// Mitsubishi GX Works2 project: 步进电机画圆(王)   PLC: FX3U/FX3UC

PROGRAM MAIN
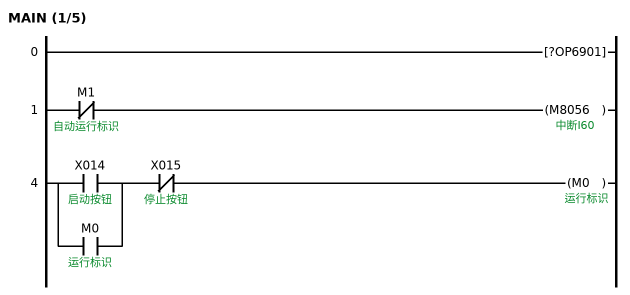
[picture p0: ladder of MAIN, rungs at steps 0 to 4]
0     ?OP6901
        [note] 允许中断(10ms中断一次)
1     LDI     M1  ; 自动运行标识
      OUT     M8056  ; 中断I60
4     LD      X014  ; 启动按钮
      OR      M0  ; 运行标识
      ANI     X015  ; 停止按钮
      OUT     M0  ; 运行标识
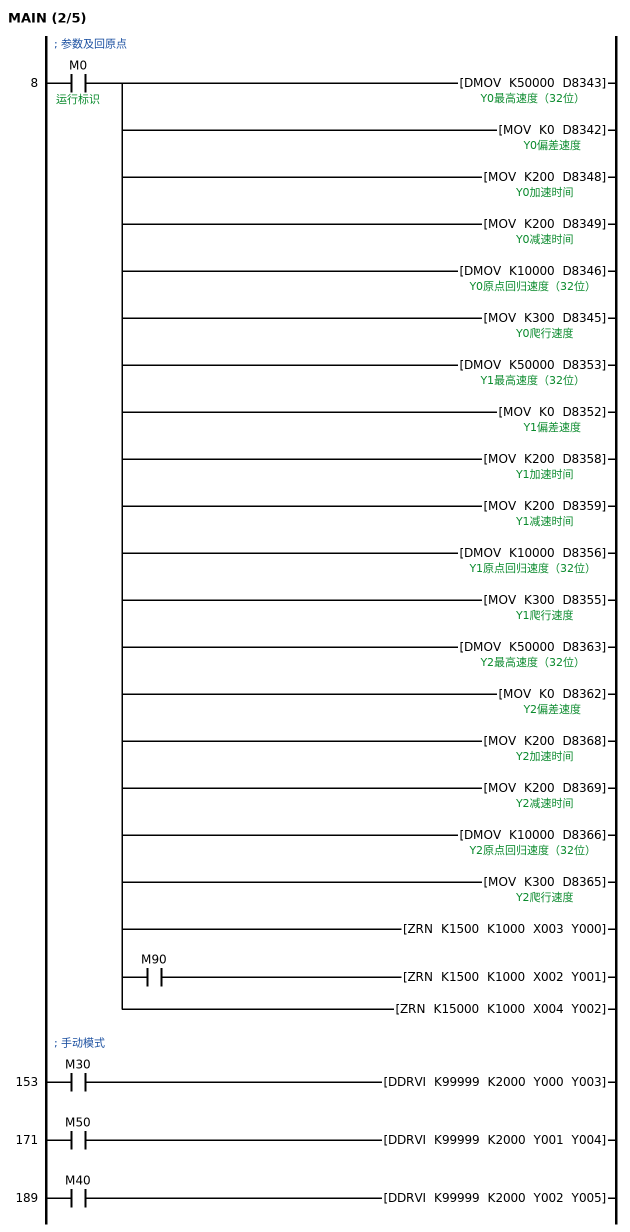
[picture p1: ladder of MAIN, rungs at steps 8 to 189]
; 参数及回原点
8     LD      M0  ; 运行标识
      DMOV    K50000 D8343  ; Y0最高速度（32位）
      MOV     K0 D8342  ; Y0偏差速度
      MOV     K200 D8348  ; Y0加速时间
      MOV     K200 D8349  ; Y0减速时间
      DMOV    K10000 D8346  ; Y0原点回归速度（32位）
      MOV     K300 D8345  ; Y0爬行速度
      DMOV    K50000 D8353  ; Y1最高速度（32位）
      MOV     K0 D8352  ; Y1偏差速度
      MOV     K200 D8358  ; Y1加速时间
      MOV     K200 D8359  ; Y1减速时间
      DMOV    K10000 D8356  ; Y1原点回归速度（32位）
      MOV     K300 D8355  ; Y1爬行速度
      DMOV    K50000 D8363  ; Y2最高速度（32位）
      MOV     K0 D8362  ; Y2偏差速度
      MOV     K200 D8368  ; Y2加速时间
      MOV     K200 D8369  ; Y2减速时间
      DMOV    K10000 D8366  ; Y2原点回归速度（32位）
      MOV     K300 D8365  ; Y2爬行速度
      ZRN     K1500 K1000 X003 Y000
        [note] Y0轴回归原点
      MPS
      AND     M90
      ZRN     K1500 K1000 X002 Y001
        [note] Y1轴回归原点
      MPP
      ZRN     K15000 K1000 X004 Y002
        [note] Y2轴回归原点
; 手动模式
153   LD      M30
      DDRVI   K99999 K2000 Y000 Y003
        [note] 右移
171   LD      M50
      DDRVI   K99999 K2000 Y001 Y004
        [note] 上移
189   LD      M40
      DDRVI   K99999 K2000 Y002 Y005
        [note] 前移
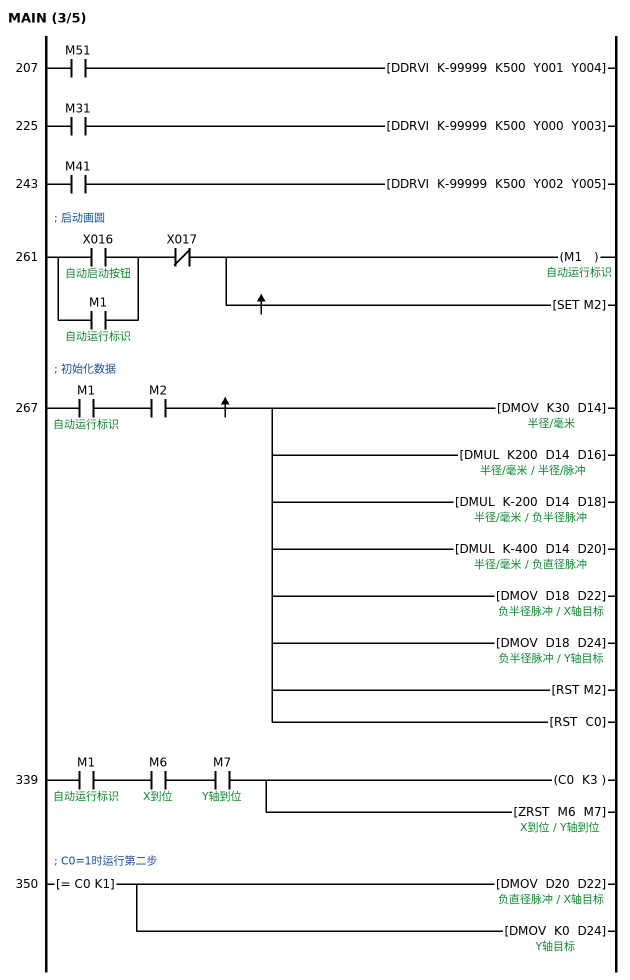
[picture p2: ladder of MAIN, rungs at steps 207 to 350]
207   LD      M51
      DDRVI   K-99999 K500 Y001 Y004
        [note] 下移
225   LD      M31
      DDRVI   K-99999 K500 Y000 Y003
        [note] 左移
243   LD      M41
      DDRVI   K-99999 K500 Y002 Y005
        [note] 后移
; 启动画圆
261   LD      X016  ; 自动启动按钮
      OR      M1  ; 自动运行标识
      ANI     X017
      OUT     M1  ; 自动运行标识
      MEP
      SET     M2
; 初始化数据
267   LD      M1  ; 自动运行标识
      AND     M2
      MEP
      DMOV    K30 D14  ; 半径/毫米
        [note] 半径设定/毫米
      DMUL    K200 D14 D16  ; 半径/脉冲
        [note] 2000细分200脉冲每毫米
      DMUL    K-200 D14 D18  ; 负半径脉冲
        [note] 2000细200脉冲每毫米
      DMUL    K-400 D14 D20  ; 负直径脉冲
        [note] 2000细分200脉冲每毫米
      DMOV    D18 D22  ; X轴目标
        [note] 第一步X轴目标
      DMOV    D18 D24  ; Y轴目标
        [note] 第一步Y轴目标
      RST     M2
      RST     C0
339   LD      M1  ; 自动运行标识
      AND     M6  ; X到位
      AND     M7  ; Y轴到位
      OUT     C0 K3
      ZRST    M6 M7
; C0=1时运行第二步
350   LD=     C0 K1
      DMOV    D20 D22
        [note] 第二步X轴目标
      DMOV    K0 D24
        [note] 第二步Y轴目标
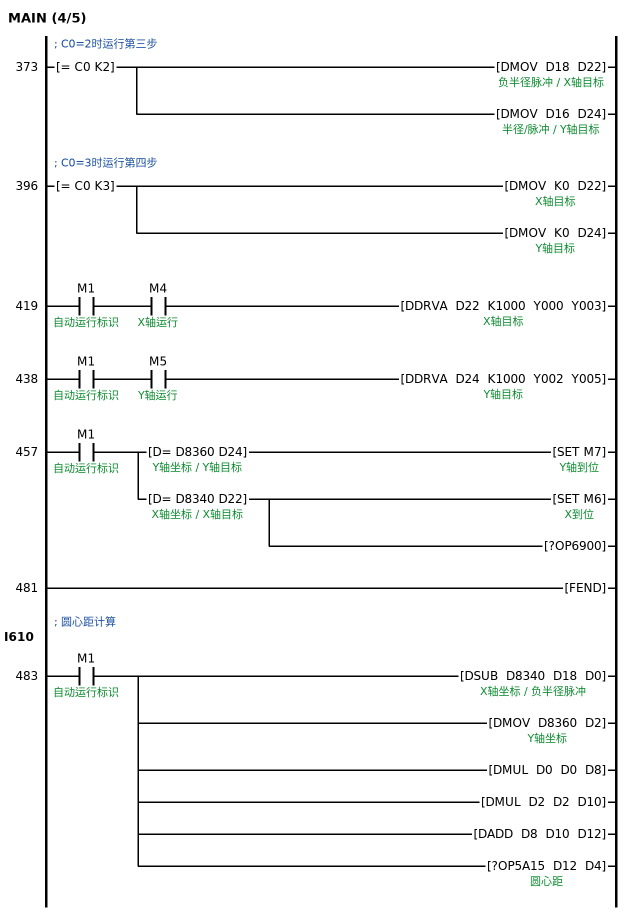
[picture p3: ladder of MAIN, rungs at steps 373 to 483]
; C0=2时运行第三步
373   LD=     C0 K2
      DMOV    D18 D22
        [note] 第三步X轴目标
      DMOV    D16 D24
        [note] 第三步Y轴目标
; C0=3时运行第四步
396   LD=     C0 K3
      DMOV    K0 D22
        [note] 第四步X骤目标
      DMOV    K0 D24
        [note] 第四步Y骤目标
419   LD      M1  ; 自动运行标识
      AND     M4  ; X轴运行
      DDRVA   D22 K1000 Y000 Y003
        [note] X轴绝对运行指令
438   LD      M1  ; 自动运行标识
      AND     M5  ; Y轴运行
      DDRVA   D24 K1000 Y002 Y005
        [note] Y轴绝对运行指令
457   LD      M1  ; 自动运行标识
      MPS
      ANDD=   D8360 D24  ; Y轴坐标 / Y轴目标
      SET     M7  ; Y轴到位
      MPP
      ANDD=   D8340 D22  ; X轴坐标 / X轴目标
      SET     M6  ; X到位
      ?OP6900
481   FEND
        [note] 中断程序开始
; 圆心距计算
      I610
483   LD      M1  ; 自动运行标识
      DSUB    D8340 D18 D0
      DMOV    D8360 D2
      DMUL    D0 D0 D8
      DMUL    D2 D2 D10
      DADD    D8 D10 D12
      ?OP5A15 D12 D4  ; 圆心距
        [note] 圆心距
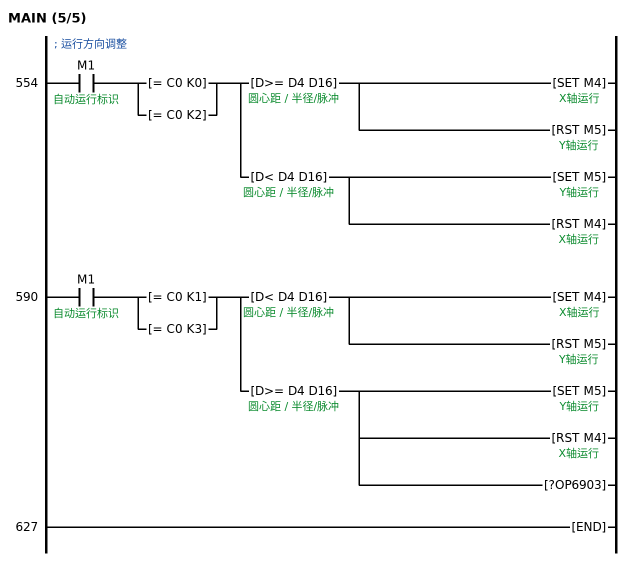
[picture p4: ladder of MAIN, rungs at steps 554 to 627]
; 运行方向调整
554   LD      M1  ; 自动运行标识
      LD=     C0 K0
      OR=     C0 K2
      ANB
      MPS
      ANDD>=  D4 D16  ; 圆心距 / 半径/脉冲
      SET     M4  ; X轴运行
      RST     M5  ; Y轴运行
      MPP
      ANDD<   D4 D16  ; 圆心距 / 半径/脉冲
      SET     M5  ; Y轴运行
      RST     M4  ; X轴运行
590   LD      M1  ; 自动运行标识
      LD=     C0 K1
      OR=     C0 K3
      ANB
      MPS
      ANDD<   D4 D16  ; 圆心距 / 半径/脉冲
      SET     M4  ; X轴运行
      RST     M5  ; Y轴运行
      MPP
      ANDD>=  D4 D16  ; 圆心距 / 半径/脉冲
      SET     M5  ; Y轴运行
      RST     M4  ; X轴运行
      ?OP6903
        [note] 中断程序结束
627   END
END_PROGRAM
